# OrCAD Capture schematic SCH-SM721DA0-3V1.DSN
size C; title: AD PLUS; rev: 1.0; note: <>
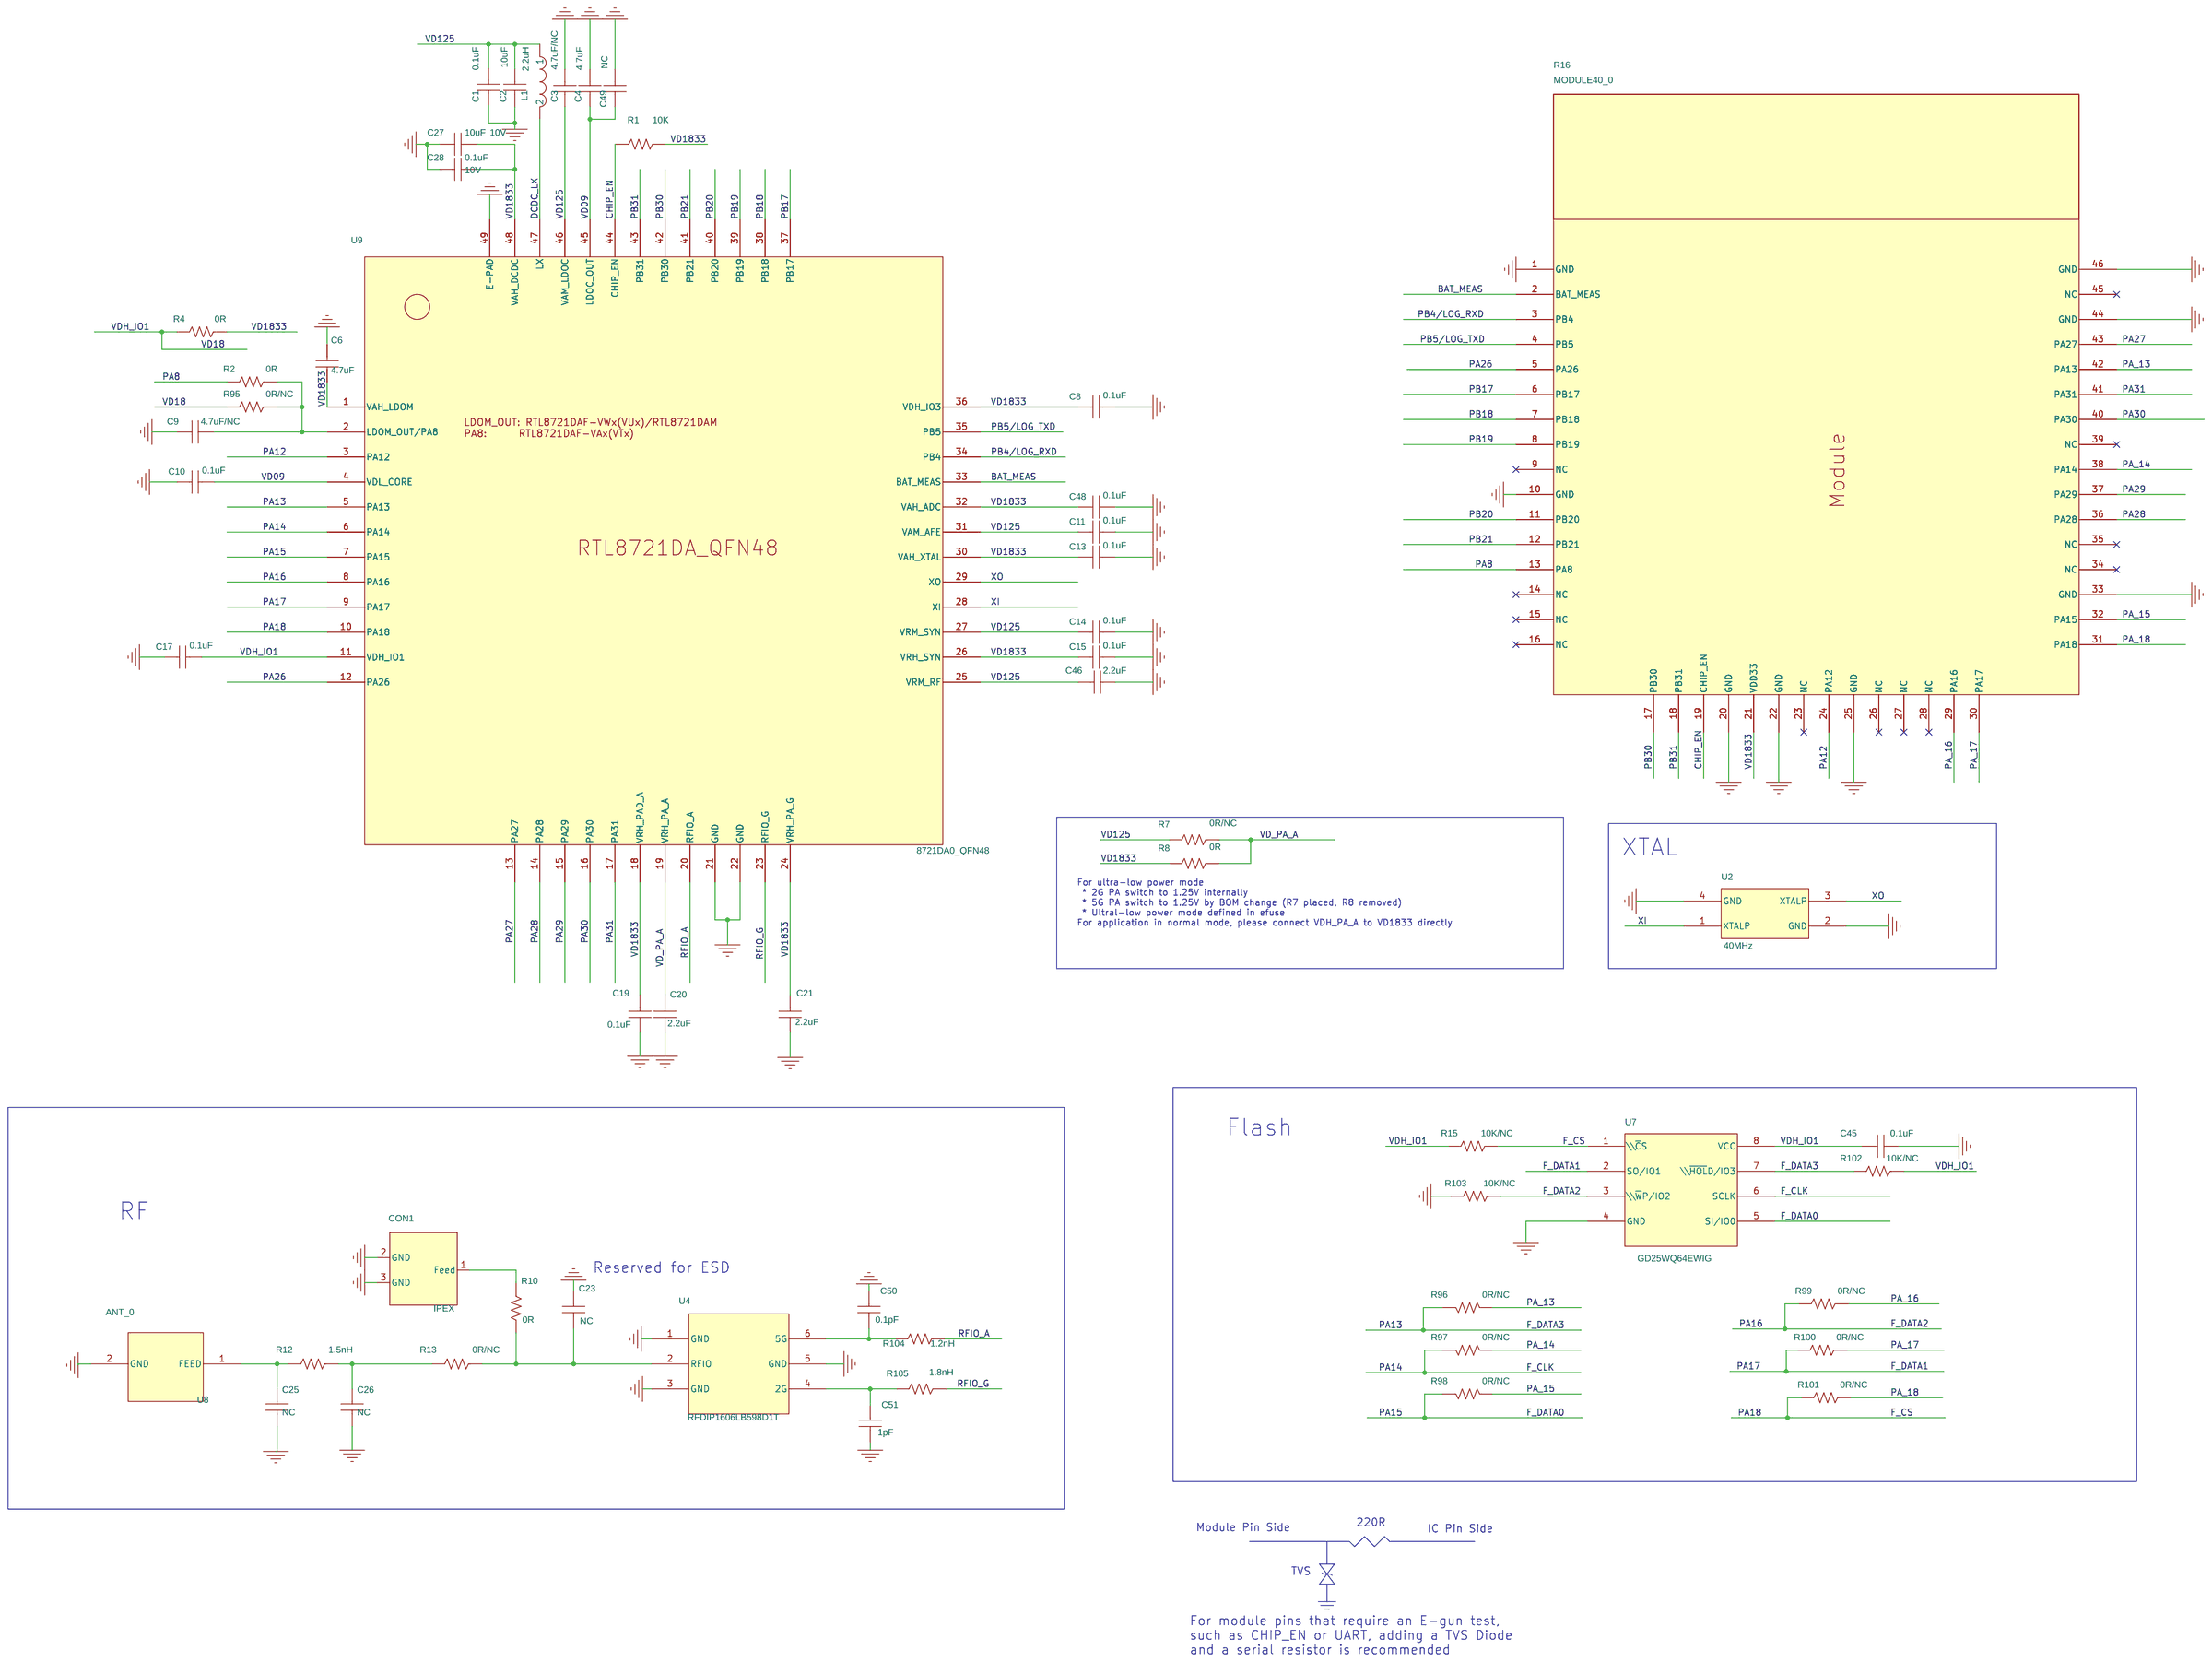
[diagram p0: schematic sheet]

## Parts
C1  0.1uF  [C0201]
C2  10uF  [C0402]
C3  4.7uF/NC  [C0402]
C4  4.7uF  [C0402]
C6  4.7uF  [C0402]
C8  0.1uF  [C0201]
C9  4.7uF/NC  [C0402]
C10  0.1uF  [C0201]
C11  0.1uF  [C0201]
C13  0.1uF  [C0201]
C14  0.1uF  [C0201]
C15  0.1uF  [C0201]
C17  0.1uF  [C0201]
C19  0.1uF  [C0201]
C20  2.2uF  [C0402]
C21  2.2uF  [C0402]
C23  NC  [C0201]
C25  NC  [C0201]
C26  NC  [C0201]
C27  10uF  [C0402]
C28  0.1uF  [C0201]
C45  0.1uF  [C0201]
C46  2.2uF  [C0402]
C48  0.1uF  [C0201]
C49  NC  [C0402]
C50  0.1pF  [C0201]
C51  1pF  [C0201]
CON1  IPEX  [IPEX3-1.35-0.7X2.2]
L1  2.2uH  [L2016]
R1  10K  [R0201]
R2  0R  [R0201]
R4  0R  [R0201]
R7  0R/NC  [R0402]
R8  0R  [R0402]
R10  0R  [R0201]
R12  1.5nH  [R0201]
R13  0R/NC  [R0201]
R15  10K/NC  [R0201]
R16  MODULE40_0  [MODULE46-16X25]
R95  0R/NC  [R0201]
R96  0R/NC  [R0201]
R97  0R/NC  [R0201]
R98  0R/NC  [R0201]
R99  0R/NC  [R0201]
R100  0R/NC  [R0201]
R101  0R/NC  [R0201]
R102  10K/NC  [R0201]
R103  10K/NC  [R0201]
R104  1.2nH  [R0201]
R105  1.8nH  [R0201]
U2  40MHz  [XTAL-2016]
U4  RFDIP1606LB598D1T  [DPX1608-6-0.5-0.25X0.6]
U7  GD25WQ64EWIG  [SOIC8-1.27-150-0.6X1.4]
U8  ANT_0  [TP]
U9  8721DA0_QFN48  [QFN48-0.4-6X6-EP4.7]

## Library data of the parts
C1 C8 C10 C11 C13-C15 C17 C19 C45 C48 = CAPACITOR_NON-POL_0: Part Number: 0201X104K100CT; Part Type: Ceramic; Tolerance,Voltage,Dielectric,Lead Free(Y/N): ±10%，10V，X5R; Datasheet: \\172.29.17.1\cn\WLAN\WLAN2\boarddesignLIB\04_component_database\Datasheet\Capacitor\Capacitor_Walsin_MLCC.pdf
C2 = CAPACITOR_NON-POL_0: Part Number: 0402X106K160CT; Voltage: 16V; Datasheet: \\172.29.17.1\cn\WLAN\WLAN2\boarddesignLIB\54_component_database\Datasheet\Capacitor\Capacitor_Walsin_MLCC.pdf
C3 C4 C6 C9 C49 = CAPACITOR_NON-POL_0: Part Number: 0402X475M160CT; Part Type: Ceramic; Tolerance,Voltage,Dielectric,Lead Free(Y/N): ±20%,16V,X5R; Datasheet: \\172.29.17.1\cn\WLAN\WLAN2\boarddesignLIB\147_component_database\Datasheet\Capacitor\Capacitor_Walsin_MLCC.pdf
C20 C21 C46 = CAPACITOR_NON-POL_0: Part Number: 0402X225K250CT; Part Type: Ceramic; Tolerance,Voltage,Dielectric,Lead Free(Y/N): ±10%,25V,X5R; Datasheet: \\172.29.17.1\cn\WLAN\WLAN2\boarddesignLIB\93_component_database\Datasheet\Capacitor\Capacitor_Walsin_MLCC.pdf
C23 C25 C26 = CAPACITOR_NON-POL_0: Part Number: RF03N1R2B250CT; Part Type: Ceramic; Tolerance,Voltage,Dielectric,Lead Free(Y/N): +/-0.1pF,25V,NPO,Y; Datasheet: \\172.29.17.1\cn\WLAN\WLAN2\boarddesignLIB\31_component_database\Datasheet\Capacitor\Capacitor_Walsin_MLCC.pdf
C27 = CAPACITOR_NON-POL_0: Part Number: 0402X106M100CT; Voltage: 10V; Datasheet: \\172.29.17.1\cn\WLAN\WLAN2\boarddesignLIB\53_component_database\Datasheet\Capacitor\Capacitor_Walsin_MLCC.pdf
C28 = CAPACITOR_NON-POL_0: Part Number: 0201X104K100CT; Voltage: 10V; Datasheet: \\172.29.17.1\cn\WLAN\WLAN2\boarddesignLIB\04_component_database\Datasheet\Capacitor\Capacitor_Walsin_MLCC.pdf
C50 C51 = CAPACITOR_NON-POL_0: ±20%,10V,X5R; Manufacturer: WALSIN; Part Number: 0201X105M100CT; Voltage: 10V; Datasheet: \\172.29.17.1\cn\WLAN\WLAN2\boarddesignLIB\82_component_database\Datasheet\Capacitor\Capacitor_Walsin_MLCC.pdf
CON1 = TP_0: IPEX大头，IPEX1; Part Number: RFCSR-N3300-TP40; Datasheet: \\172.29.17.1\cn\WLAN\WLAN2\boarddesignLIB\01_component_database\Datasheet\Connector\RF Connector_Argosy_RFCSR-N3300-TP40_APL_Realtek (2017-03-06).pdf
L1 = Inductor_Power: Part Number: MHCD201610B-2R2M-A8L; Õ`²îÖµTolerance(nH/%),Q‚Ž(min): 1.8A,±20%
R1 R15 R102 R103 = RES_0: Part Number: WR02X103 JAL; Tolerance,Voltage,Dielectric,Lead Free(Y/N): +/-5%; Datasheet: \\172.29.17.1\cn\WLAN\WLAN2\boarddesignLIB\40_component_database\Datasheet\Resistor\Resistor_Walsin_chipR.pdf
R2 R4 R10 R12 R13 R95-R101 = RES_0: Part Number: WR02X000PTL; Part type: Chip Resistor; Tolerance,Voltage,Dielectric,Lead Free(Y/N): JUMPER; Datasheet: \\172.29.17.1\cn\WLAN\WLAN2\boarddesignLIB\62_component_database\Datasheet\ResistorResistor_Walsin_chipR.pdf
R7 R8 = RES_0: Part Number: WR04X000PTL; Tolerance,Voltage,Dielectric,Lead Free(Y/N): JUMPER; Datasheet: \\172.29.17.1\cn\WLAN\WLAN2\boarddesignLIB\64_component_database\Datasheet\Resistor\Resistor_Walsin_chipR.pdf
R16 = MODULE40_3
R104 R105 = RES_0: +/-5%; Manufacturer: WALSIN; Part Number: WR02X103 JAL; Datasheet: \\172.29.17.1\cn\WLAN\WLAN2\boarddesignLIB\40_component_database\Datasheet\Resistor\Resistor_Walsin_chipR.pdf
U2 = XTAL_0: 9pf，25ohms，10ppm，-55-125度; Part Number: E1SB40E00090FE
U4 = DPX_0: 2nd harmonic suppressed; Datasheet: \\172.29.17.1\cn\WLAN\WLAN2\boarddesignLIB\01_component_database\Datasheet\RF Chip\DPX_Walsin_RFDIP1606LB598D1T_V01.pdf
U7 = Flash_0: Used for Module; Part Number: GD25Q16C; Datasheet: \\172.29.17.1\cn\WLAN\WLAN2\boarddesignLIB\01_component_database\Datasheet\Memory\FLASH_GigaDevice_GD25Q16CTIG.pdf
U8 = ANT_0
U9 = AmebaLite_QFN48_D+_0: AmebaDplus QFN48; Manufacturer: Realtek; Part Number: RTL8721DA0

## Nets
GND: C1.1 C2.2 C3.2 C4.2 C6.2 C8.2 C9.1 C10.1 C11.2 C13.2 C14.2 C15.2 C17.1 C19.1 C20.1 C21.1 C23.1 C25.2 C26.2 C27.1 C28.1 C45.1 C46.1 C48.2 C49.2 C50.1 C51.2 CON1.2(GND) CON1.3(GND) R16.1(GND) R16.10(GND) R16.20(GND) R16.22(GND) R16.25(GND) R16.33(GND) R16.44(GND) R16.46(GND) R103.1 U2.2(GND) U2.4(GND) U4.1(GND) U4.3(GND) U4.5(GND) U7.4(GND) U8.2(GND) U9.21(GND) U9.22(GND) U9.49(E-PAD)
BAT_MEAS: R16.2(BAT_MEAS) U9.33(BAT_MEAS)
CHIP_EN: R1.2 R16.19(CHIP_EN) U9.44(CHIP_EN)
DCDC_LX: L1.2 U9.47(LX)
F_CLK: R97.2 U7.6(SCLK) U9.6(PA14)
F_CS: R15.2 R101.1 U7.1(\\~{C}S) U9.10(PA18)
F_DATA0: R98.2 U7.5(SI/IO0) U9.7(PA15)
F_DATA1: R100.1 U7.2(SO/IO1) U9.9(PA17)
F_DATA2: R99.1 R103.2 U7.3(\\~{W}P/IO2) U9.8(PA16)
F_DATA3: R96.2 R102.1 U7.7(\\~{HOL}D/IO3) U9.5(PA13)
PA8: R2.1 R16.13(PA8)
PA12: R16.24(PA12) U9.3(PA12)
PA26: R16.5(PA26) U9.12(PA26)
PA27: R16.43(PA27) U9.13(PA27)
PA28: R16.36(PA28) U9.14(PA28)
PA29: R16.37(PA29) U9.15(PA29)
PA30: R16.40(PA30) U9.16(PA30)
PA31: R16.41(PA31) U9.17(PA31)
PA_13: R16.42(PA13) R96.1
PA_14: R16.38(PA14) R97.1
PA_15: R16.32(PA15) R98.1
PA_16: R16.29(PA16) R99.2
PA_17: R16.30(PA17) R100.2
PA_18: R16.31(PA18) R101.2
PB4/LOG_RXD: R16.3(PB4) U9.34(PB4)
PB5/LOG_TXD: R16.4(PB5) U9.35(PB5)
PB17: R16.6(PB17) U9.37(PB17)
PB18: R16.7(PB18) U9.38(PB18)
PB19: R16.8(PB19) U9.39(PB19)
PB20: R16.11(PB20) U9.40(PB20)
PB21: R16.12(PB21) U9.41(PB21)
PB30: R16.17(PB30) U9.42(PB30)
PB31: R16.18(PB31) U9.43(PB31)
RFIO_A: R104.2 U9.20(RFIO_A)
RFIO_G: R105.2 U9.23(RFIO_G)
VD09: C4.1 C10.2 C49.1 U9.4(VDL_CORE) U9.45(LDOC_OUT)
VD18: C17.2 C45.2 R4.1 R15.1 R95.1 R102.2 U7.8(VCC) U9.11(VDH_IO1)
VD125: C1.2 C2.1 C3.1 C11.1 C14.1 C46.2 L1.1 R7.1 U9.25(VRM_RF) U9.27(VRM_SYN) U9.31(VAM_AFE) U9.46(VAM_LDOC)
VD1833: C6.1 C8.1 C13.1 C15.1 C19.2 C21.2 C27.2 C28.2 C48.1 R1.1 R4.2 R8.1 R16.21(VDD33) U9.1(VAH_LDOM) U9.18(VRH_PAD_A) U9.24(VRH_PA_G) U9.26(VRH_SYN) U9.30(VAH_XTAL) U9.32(VAH_ADC) U9.36(VDH_IO3) U9.48(VAH_DCDC)
VD_PA_A: C20.2 R7.2 R8.2 U9.19(VRH_PA_A)
XI: U2.1(XTALP) U9.28(XI)
XO: U2.3(XTALP) U9.29(XO)
N16320530: C23.2 R10.1 R13.2 U4.2(RFIO)
N16379016: C50.2 R104.1 U4.6(5G)
N16379053: C51.1 R105.1 U4.4(2G)
N16457890: C9.2 R2.2 R95.2 U9.2(LDOM_OUT/PA8)
N16471101: C25.1 R12.1 U8.1(FEED)
N16471347: C26.1 R12.2 R13.1
N16472609: CON1.1(Feed) R10.2

Not connected (* = marked no-connect by the designer): R16 9(NC)* 14(NC)* 15(NC)* 16(NC)* 23(NC)* 26(NC)* 27(NC)* 28(NC)* 34(NC)* 35(NC)* 39(NC)* 45(NC)*

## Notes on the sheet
- XTAL
- For ultra-low power mode
   * 2G PA switch to 1.25V internally
   * 5G PA switch to 1.25V by BOM change (R7 placed, R8 removed)
   * Ultral-low power mode defined in efuse
  For application in normal mode, please connect VDH_PA_A to VD1833 directly
- Flash
- RF
- Reserved for ESD
- 220R
- Module Pin Side
- IC Pin Side
- TVS
- For module pins that require an E-gun test,
  such as CHIP_EN or UART, adding a TVS Diode
  and a serial resistor is recommended
